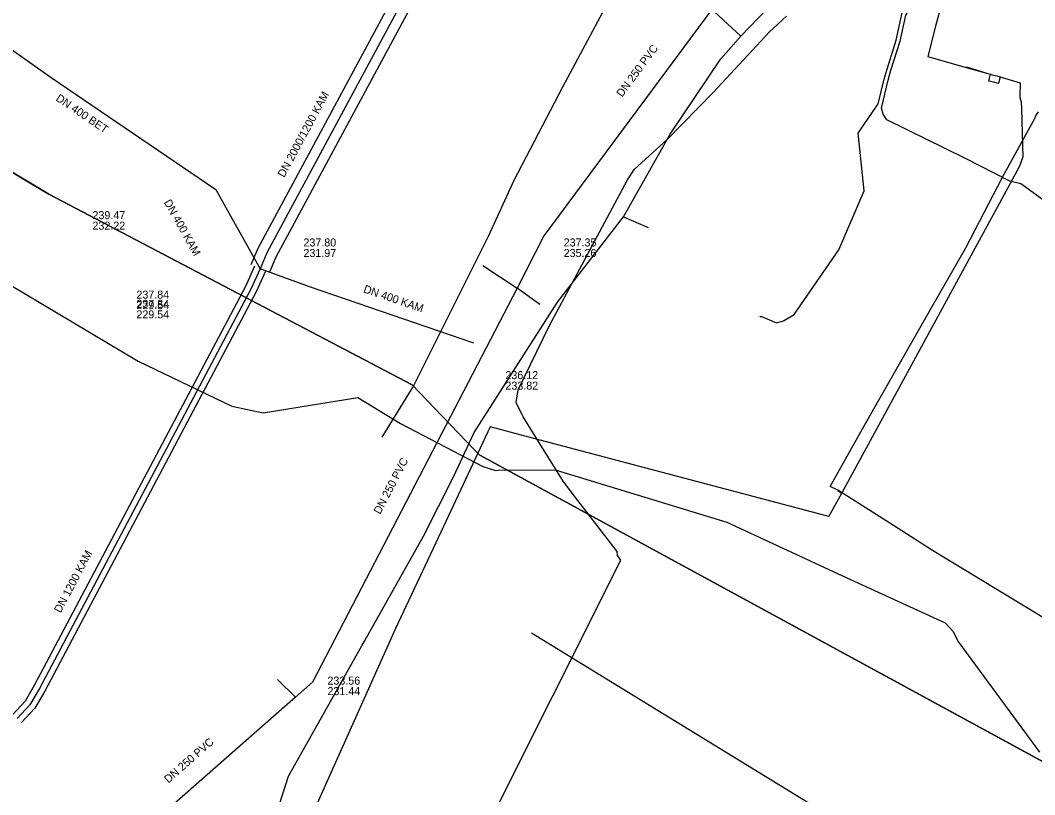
# Model space of a CAD drawing. Extents: x -598233 to -596890, y -1157848 to -1156431.
# Drawn here: x -597089.8 to -596988.4, y -1157762.5 to -1157685.2 of the extents above; entities that cross this region are included whole.
import ezdxf

# ---------------------------------------------------------------- set-up
doc = ezdxf.new("R2010")
doc.units = 0
for name, color, linetype in [('Vrstva 1', 7, 'Continuous'), ('Vrstva 10', 7, 'Continuous'), ('Vrstva 12', 7, 'Continuous'), ('Vrstva 19', 7, 'Continuous'), ('Vrstva 22', 7, 'Continuous'), ('Vrstva 4', 7, 'Continuous'), ('Vrstva 42', 7, 'Continuous'), ('Vrstva 48', 7, 'Continuous'), ('Vrstva 54', 7, 'Continuous'), ('Vrstva 55', 7, 'Continuous'), ('Vrstva 58', 7, 'Continuous'), ('Vrstva 60', 7, 'Continuous'), ('Vrstva 9', 7, 'Continuous')]:
    doc.layers.add(name, color=color, linetype=linetype)

msp = doc.modelspace()

# ---------------------------------------------------------------- linework, layer by layer
at = {"layer": 'Vrstva 1'}
for p, q in [((-597043.6, -1157709.69), (-597040.15, -1157711.95)), ((-597037.89, -1157713.56), (-597040.15, -1157711.95)), ((-597064.09, -1157751.02), (-597062.31, -1157752.79))]:
    msp.add_line(p, q, dxfattribs=at)
for points in [[(-597013.99, -1157675.02), (-597015.36, -1157676.87), (-597015.85, -1157677.53), (-597037.49, -1157706.73)], [(-597037.49, -1157706.73), (-597040.15, -1157711.95), (-597060.61, -1157751.3)], [(-596978.37, -1157783.4), (-597038.73, -1157746.39)], [(-597060.61, -1157751.3), (-597062.31, -1157752.79), (-597080.49, -1157768.78)]]:
    msp.add_lwpolyline(points, dxfattribs=at)
at = {"layer": 'Vrstva 10'}
for points in [[(-597047.26, -1157673.04), (-597066.06, -1157707.97), (-597066.77, -1157709.6)], [(-597045.5, -1157673.99), (-597064.26, -1157708.84), (-597064.93, -1157710.4)], [(-597066.4, -1157709.75), (-597067.3, -1157711.77), (-597088.4, -1157751.62), (-597089.33, -1157753.19), (-597090.55, -1157754.53)], [(-597065.3, -1157710.25), (-597066.22, -1157712.3), (-597087.36, -1157752.21), (-597088.36, -1157753.91), (-597089.67, -1157755.33)]]:
    msp.add_lwpolyline(points, dxfattribs=at)
at = {"layer": 'Vrstva 12'}
for points in [[(-597034.41, -1157732.71), (-597035.55, -1157731.21), (-597039.54, -1157724.78), (-597040.27, -1157723.37), (-597040.04, -1157722.1), (-597036.91, -1157715.69), (-597029.14, -1157701.11), (-597028.44, -1157700.07), (-597025.18, -1157697.11), (-597020.57, -1157692.39), (-597014.95, -1157686.34), (-597013.23, -1157684.78)], [(-597043.45, -1157766.35), (-597029.79, -1157739.12), (-597030.12, -1157738.64), (-597030.17, -1157738.23), (-597034.41, -1157732.71)]]:
    msp.add_lwpolyline(points, dxfattribs=at)
at = {"layer": 'Vrstva 19'}
for points in [[(-597027.92, -1157677.37), (-597017.82, -1157686.78)], [(-597046.52, -1157730.8), (-597044.44, -1157726.35), (-597036.14, -1157713.35), (-597029.53, -1157704.83), (-597024.88, -1157696.55), (-597019.79, -1157689.04), (-597017.82, -1157686.78), (-597012.62, -1157681.34), (-597011.01, -1157679.98)], [(-597029.53, -1157704.83), (-597027.06, -1157705.89)], [(-597055.65, -1157747.6), (-597055.42, -1157747.19), (-597049.53, -1157736.73), (-597046.52, -1157730.8)], [(-597068.25, -1157777.06), (-597063.01, -1157760.68), (-597055.65, -1157747.6)]]:
    msp.add_lwpolyline(points, dxfattribs=at)
at = {"layer": 'Vrstva 22'}
for points in [[(-597009, -1157734.74), (-597038.36, -1157726.98), (-597042.85, -1157725.8), (-597048.29, -1157737.37), (-597052.31, -1157745.93), (-597068.29, -1157781.63), (-597068.57, -1157782.25), (-597069.3, -1157783.87), (-597069.52, -1157784.38), (-597069.75, -1157784.88), (-597070.02, -1157785.41), (-597070.37, -1157786.1), (-597078.6, -1157807.09), (-597134.97, -1157778.57), (-597188.98, -1157751.64), (-597260.05, -1157717.7), (-597353.38, -1157680.59), (-597353.4, -1157680.57), (-597439.93, -1157655.49), (-597531.04, -1157635.25), (-597620.04, -1157616.48), (-597669.81, -1157606.33)], [(-596994.94, -1157684.09), (-596997.71, -1157683.44), (-596998.34, -1157685.79), (-596999.13, -1157688.79), (-596995.28, -1157689.89), (-596993.13, -1157690.5)], [(-596993.13, -1157690.5), (-596992.86, -1157690.57), (-596992.79, -1157690.59), (-596992.39, -1157690.71), (-596992.24, -1157690.75), (-596991.91, -1157690.84), (-596991.79, -1157690.88), (-596989.89, -1157691.42), (-596989.93, -1157692.91), (-596989.79, -1157693.38), (-596989.76, -1157694.01), (-596989.62, -1157698.91)], [(-596991.91, -1157690.84), (-596992, -1157691.19), (-596992.07, -1157691.5), (-596992.57, -1157691.37), (-596993.02, -1157691.26), (-596992.96, -1157690.98), (-596992.86, -1157690.57)], [(-596926.44, -1157768.84), (-596927.67, -1157769.15), (-596928.26, -1157769.3), (-596931.83, -1157770.36), (-596952.59, -1157760.68), (-596968.99, -1157753.62), (-596979.8, -1157749), (-596986.45, -1157745.55), (-596998.64, -1157738.16), (-597002.54, -1157735.64), (-597008.12, -1157732.13), (-597008.87, -1157731.74), (-597005.36, -1157725.46), (-596998.96, -1157714.24), (-596995.33, -1157707.9), (-596991.66, -1157700.85), (-596988.41, -1157694.92), (-596988.32, -1157694.72), (-596988.22, -1157694.56), (-596988.07, -1157694.33)], [(-597009, -1157734.74), (-597007.73, -1157732.41), (-596991.11, -1157701.9), (-596989.93, -1157699.74), (-596989.62, -1157698.91)]]:
    msp.add_lwpolyline(points, dxfattribs=at)
at = {"layer": 'Vrstva 42'}
for points in [[(-597015.87, -1157714.84), (-597015.82, -1157714.74), (-597014.23, -1157715.42), (-597013.55, -1157715.21), (-597012.47, -1157714.59), (-597008.02, -1157708.1), (-597005.48, -1157702.21), (-597006.07, -1157696.45), (-597004.07, -1157693.55), (-597003.49, -1157691.08), (-597003.2, -1157690.06), (-597002.29, -1157687.17), (-597001.65, -1157684.27), (-597001.44, -1157684.03), (-597001.11, -1157684.12)], [(-596984.62, -1157711.42), (-596984.59, -1157711.37), (-596984.94, -1157710.87), (-596984.99, -1157710.47), (-596984.74, -1157709.55), (-596985.58, -1157706.8), (-596987.08, -1157703.52), (-596989.84, -1157701.53), (-596990.92, -1157701.26), (-596995.43, -1157698.97), (-597003.21, -1157695.14), (-597003.59, -1157694.56), (-597003.75, -1157693.95), (-597003.1, -1157691.18), (-597002.82, -1157690.18), (-597001.9, -1157687.27), (-597001.33, -1157684.68), (-597001.17, -1157684.42)]]:
    msp.add_lwpolyline(points, dxfattribs=at)
at = {"layer": 'Vrstva 48'}
for points in [[(-596995.26, -1157689.83), (-596993.13, -1157690.5)], [(-597008.12, -1157732.13), (-597008.13, -1157732.16)], [(-597008.13, -1157732.16), (-597007.73, -1157732.41)]]:
    msp.add_lwpolyline(points, dxfattribs=at)
at = {"layer": 'Vrstva 54'}
for p, q in [((-597093.49, -1157698.66), (-597086.96, -1157702.56)), ((-597086.96, -1157702.56), (-597050.66, -1157721.6)), ((-597050.66, -1157721.6), (-597049.19, -1157723.13)), ((-597049.19, -1157723.13), (-597044.48, -1157728.02)), ((-597044.48, -1157728.02), (-597043.89, -1157728.64)), ((-597043.89, -1157728.64), (-596966.78, -1157770.59))]:
    msp.add_line(p, q, dxfattribs=at)
at = {"layer": 'Vrstva 55'}
msp.add_lwpolyline([(-596939.31, -1157598.75), (-596939.07, -1157599.4), (-596937.95, -1157599.56), (-596938.19, -1157602.53), (-596939.79, -1157606.06), (-596943.8, -1157609.03), (-596945.57, -1157610.39), (-596951.42, -1157615.61), (-596965.46, -1157627.96), (-596969.31, -1157631.16), (-596978.29, -1157638.7), (-596987.91, -1157646.32), (-596996.9, -1157653.86), (-597001.31, -1157657.39), (-597009.89, -1157665.09), (-597021.36, -1157675.11), (-597023.6, -1157677.44), (-597028.01, -1157680.65), (-597031.62, -1157684.42), (-597035.63, -1157691.87), (-597040.53, -1157701.26), (-597043.01, -1157706.71), (-597050.47, -1157721.63), (-597053.67, -1157726.84)], dxfattribs=at)
at = {"layer": 'Vrstva 58'}
for points in [[(-597109.7, -1157699.89), (-597106.15, -1157701.11), (-597101.09, -1157703.39), (-597099.55, -1157705.94), (-597091.06, -1157711.48), (-597078.02, -1157719.22), (-597068.67, -1157723.74), (-597065.52, -1157724.41), (-597056.06, -1157722.87), (-597051.81, -1157725.47), (-597043.57, -1157729.76), (-597042.33, -1157730.14), (-597042.07, -1157730.12)], [(-597042.07, -1157730.12), (-597036.36, -1157730.08), (-597019.2, -1157735.3), (-597007.65, -1157740.69), (-596997.4, -1157745.37), (-596996.59, -1157746.24), (-596996.12, -1157747.19), (-596987.95, -1157758.29)]]:
    msp.add_lwpolyline(points, dxfattribs=at)
at = {"layer": 'Vrstva 60'}
for points in [[(-597179.87, -1157644.26), (-597115.94, -1157685.24), (-597093.49, -1157698.66), (-597086.96, -1157702.56), (-597050.66, -1157721.6), (-597049.19, -1157723.13), (-597044.48, -1157728.02), (-597043.89, -1157728.64), (-596966.78, -1157770.59), (-596991, -1157796.97), (-596991.35, -1157797.35), (-596994.58, -1157800.82), (-596995.24, -1157801.52), (-596996.93, -1157803.34), (-596977.24, -1157811.71)], [(-596966.78, -1157770.59), (-597043.89, -1157728.64), (-597044.48, -1157728.02), (-597049.19, -1157723.13), (-597050.66, -1157721.6), (-597086.96, -1157702.56), (-597093.49, -1157698.66)]]:
    msp.add_lwpolyline(points, dxfattribs=at)
at = {"layer": 'Vrstva 9'}
for p, q in [((-597107.25, -1157676.41), (-597086.71, -1157690.9)), ((-597086.71, -1157690.9), (-597070.27, -1157702.08)), ((-597070.27, -1157702.08), (-597069.9, -1157702.76)), ((-597069.9, -1157702.76), (-597065.85, -1157710)), ((-597060.81, -1157711.84), (-597065.85, -1157710)), ((-597044.47, -1157717.45), (-597060.81, -1157711.84))]:
    msp.add_line(p, q, dxfattribs=at)
for points in [[(-597046.38, -1157673.51), (-597065.16, -1157708.4), (-597065.85, -1157710)], [(-597065.85, -1157710), (-597066.76, -1157712.04), (-597087.88, -1157751.92), (-597088.85, -1157753.55), (-597090.11, -1157754.93)]]:
    msp.add_lwpolyline(points, dxfattribs=at)

# ---------------------------------------------------------------- texts
at = {"layer": 'Vrstva 12'}
for s, rotation, p in [('DN 2000/1200 KAM', 61.7076, (-597063.43, -1157700.95)), ('DN 400 BET', 325.7838, (-597086.32, -1157693.15)), ('DN 400 KAM', 299.1986, (-597075.48, -1157703.36)), ('DN 400 KAM', 341.0818, (-597055.58, -1157712.35)), ('DN 1200 KAM', 62.1086, (-597085.77, -1157744.44))]:
    msp.add_text(s, height=0.8, rotation=rotation, dxfattribs=at).set_placement(p)
for s, p in [('239.47', (-597082.59, -1157705.05)), ('232.22', (-597082.59, -1157706.1)), ('237.80', (-597061.51, -1157707.78)), ('231.97', (-597061.51, -1157708.83)), ('237.84', (-597078.2, -1157712.99)), ('237.84', (-597078.2, -1157713.91)), ('229.54', (-597078.2, -1157714.04)), ('229.54', (-597078.2, -1157714.96)), ('236.12', (-597041.33, -1157721.03)), ('233.82', (-597041.33, -1157722.08))]:
    msp.add_text(s, height=0.8, dxfattribs=at).set_placement(p)
at = {"layer": 'Vrstva 4'}
for rotation, p in [(53.4587, (-597029.67, -1157692.92)), (62.5215, (-597053.84, -1157734.59)), (41.3244, (-597075, -1157761.43))]:
    msp.add_text('DN 250 PVC', height=0.8, rotation=rotation, dxfattribs=at).set_placement(p)
for s, p in [('237.35', (-597035.51, -1157707.78)), ('235.26', (-597035.51, -1157708.83)), ('233.56', (-597059.11, -1157751.54)), ('231.44', (-597059.11, -1157752.59))]:
    msp.add_text(s, height=0.8, dxfattribs=at).set_placement(p)

doc.saveas('drawing.dxf')
